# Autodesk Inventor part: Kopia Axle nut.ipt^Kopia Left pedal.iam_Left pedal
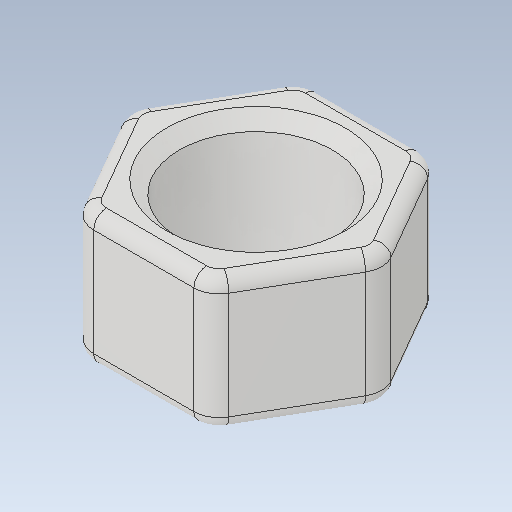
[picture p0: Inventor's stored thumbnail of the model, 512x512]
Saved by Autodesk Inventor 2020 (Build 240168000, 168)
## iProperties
Created: 2017-10
Part Number: Kopia Axle nut.ipt^Kopia Left pedal.iam_Left pedal
Material: Ogólny
Document SubType Name: Modeling
Designer: Tomasz
Density: 1 g/cm^3
Appearance: Domyślna
Sending System: SolidWorks 2017
Last Author: Tomasz
Last Saved: 2017-10-01
Author: Tomasz
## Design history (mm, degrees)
feature "Axle nut.ipt"
node "Bryła1"
